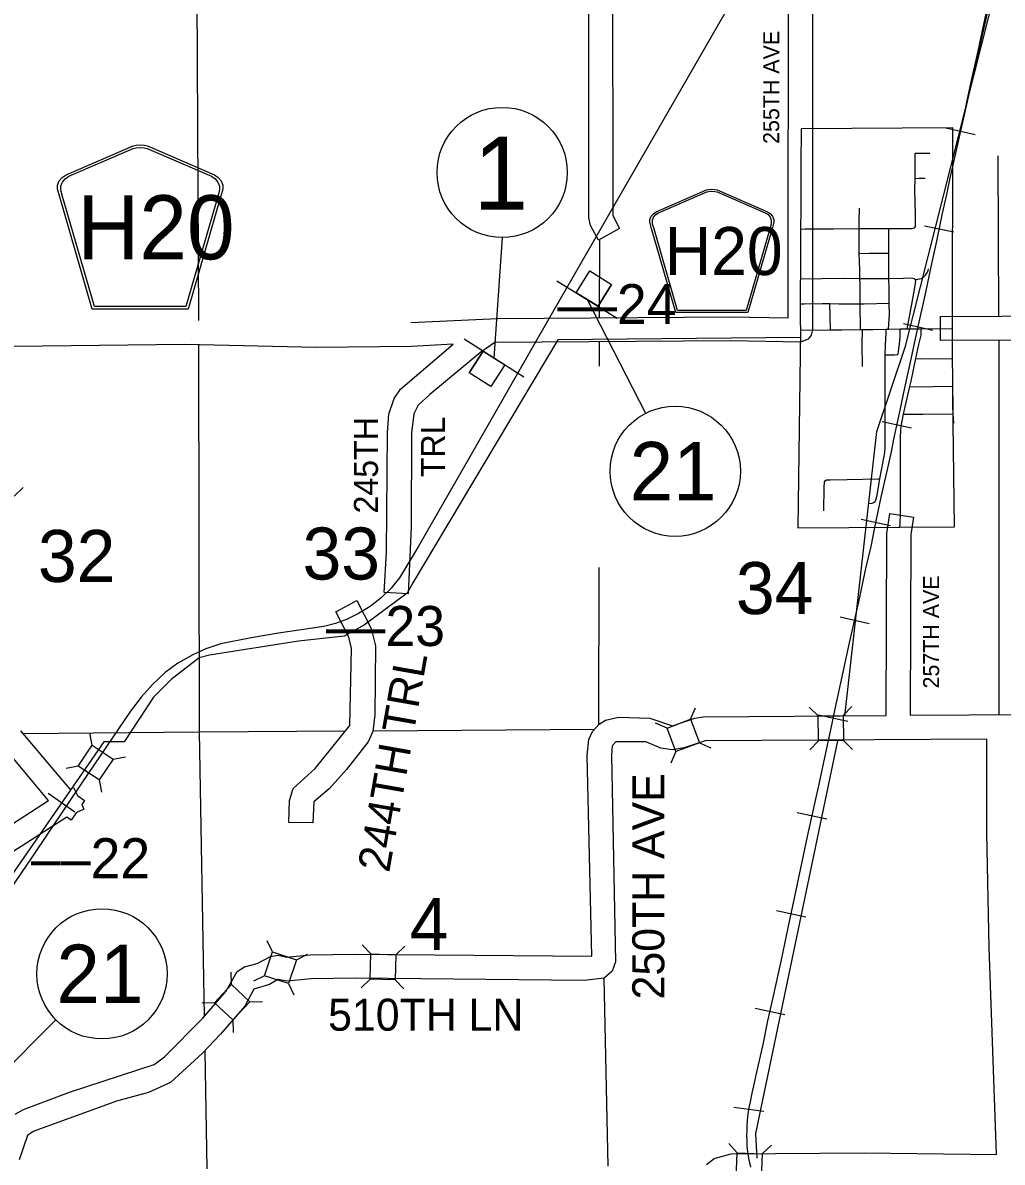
# Model space of a CAD drawing. Extents: x 10133 to 81668, y 5524 to 11018.
# Drawn here: x 18585.8 to 18891.5, y 8825.6 to 9181.4 of the extents above; entities that cross this region are included whole.
import ezdxf

# ---------------------------------------------------------------- set-up
doc = ezdxf.new("R2010")
doc.units = 0
for name, color, linetype in [('Default', 7, 'Continuous'), ('DisBoundDim', 7, 'Continuous'), ('DisCLMLOR', 7, 'Continuous'), ('DisCLMLSUR', 7, 'Continuous'), ('trf_SignNumber_Text', 7, 'Continuous')]:
    doc.layers.add(name, color=color, linetype=linetype)

msp = doc.modelspace()

# ---------------------------------------------------------------- linework, layer by layer
at = {"layer": 'Default'}
for p, q in [((18883.08, 9146.4), (18873.93, 9148.47)), ((18876.38, 9115.97), (18867.2, 9117.87)), ((18869.8, 9085.35), (18860.65, 9087.38)), ((18863.22, 9054.81), (18854.06, 9056.83)), ((18842.35, 8964.85), (18852.34, 9053.78)), ((18842.35, 8964.85), (18852.34, 9053.78)), ((18583.05, 9033.52), (18585.84, 9036.26)), ((18856.6, 9024.29), (18847.43, 9026.27)), ((18850, 8993.68), (18840.87, 8995.79)), ((18794.18, 8963.89), (18795.79, 8967.45)), ((18833.99, 8964.94), (18831.18, 8967.66)), ((18841.81, 8965.06), (18844.54, 8967.87)), ((18843.3, 8963.22), (18834.13, 8965.21)), ((18607.43, 8955.79), (18606.67, 8959.63)), ((18786.86, 8961.12), (18783.3, 8962.73)), ((18796.95, 8956.57), (18800.52, 8954.96)), ((18834.11, 8957.12), (18831.39, 8954.31)), ((18841.93, 8957.24), (18844.74, 8954.51)), ((18789.63, 8953.8), (18788.02, 8950.24)), ((18603.08, 8949.29), (18599.24, 8948.53)), ((18613.94, 8951.44), (18617.78, 8952.2)), ((18609.59, 8944.94), (18610.35, 8941.1)), ((18601.99, 8934.94), (18593.7, 8940.68)), ((18836.69, 8932.69), (18827.52, 8934.65)), ((18830.17, 8902.15), (18820.99, 8904.07)), ((18663.74, 8891.25), (18661.99, 8894.76)), ((18694.39, 8890.6), (18691.7, 8893.44)), ((18702.22, 8890.39), (18705.05, 8893.09)), ((18671.16, 8888.77), (18674.66, 8890.51)), ((18650.93, 8881.05), (18650.81, 8884.96)), ((18661.25, 8883.83), (18657.75, 8882.09)), ((18668.67, 8881.35), (18670.41, 8877.85)), ((18694.19, 8882.78), (18691.35, 8880.08)), ((18702.01, 8882.57), (18704.7, 8879.73)), ((18645.57, 8875.35), (18641.66, 8875.23)), ((18656.63, 8875.69), (18660.54, 8875.81)), ((18823.58, 8871.56), (18814.42, 8873.57)), ((18651.27, 8869.99), (18651.39, 8866.07)), ((18817.04, 8841.37), (18807.76, 8842.66)), ((18808.75, 8828.55), (18806.11, 8831.43)), ((18816.57, 8828.22), (18819.45, 8830.87))]:
    msp.add_line(p, q, dxfattribs=at)
for points in [[(18706.9, 9087.83), (18733.89, 9089.06), (18806.81, 9089.56), (18824.72, 9089.23), (18824.75, 9207.22), (18823.61, 9212.38), (18819.98, 9218.12), (18824.95, 9221.42), (18824.62, 9268.34), (18801, 9268.34), (18801.02, 9275.84), (18886.94, 9275.81), (18886.45, 9366.81)], [(18639.97, 9210.03), (18640.62, 9088.43)], [(18852.34, 9053.78), (18861.28, 9080.37), (18894.42, 9211.45)], [(18852.34, 9053.78), (18861.28, 9080.37), (18894.42, 9211.45)], [(18832.25, 9207.36), (18832.24, 9085.5), (18831.9, 9083.89), (18830.91, 9082.59), (18828.47, 9081.71), (18806.79, 9082.06), (18733.07, 9081.53), (18728.74, 9078.49), (18712.78, 9065.27), (18709.19, 9061.95), (18707.8, 9059.33), (18707.06, 9053.36), (18706.94, 9023.98), (18706.04, 9003.03), (18698.55, 9003.47), (18699.26, 9015.94), (18699.56, 9053.49), (18700.03, 9059.2), (18701.65, 9064.03), (18703.61, 9066.96), (18720.06, 9081.03), (18707.1, 9080.33), (18677.41, 9080.02), (18636.35, 9080.95), (18583.04, 9080.34)], [(18769.85, 9201.5), (18769.95, 9121.24), (18772.07, 9117.14), (18765.51, 9113.5), (18762.98, 9118.08), (18762.49, 9120.46), (18762.43, 9187.34)], [(18814.36, 9200.97), (18770.52, 9124.8), (18746.78, 9083.34), (18723.6, 9042.93), (18709.21, 9017.78), (18703.32, 9008.07), (18700.69, 9004.81), (18697.6, 9001.78), (18694.19, 8999.12), (18690.5, 8996.88), (18686.8, 8995.09), (18683.32, 8993.77), (18679.7, 8992.88), (18665.53, 8990.74), (18657.05, 8989.32), (18647.52, 8987.43), (18642.87, 8985.87), (18638.82, 8984.05), (18634.18, 8981.37), (18630.23, 8978.47), (18626.27, 8974.8), (18622.65, 8970.78), (18619.41, 8966.45), (18604.18, 8944.04), (18588.65, 8920.98), (18568.86, 8892.04)], [(18813.03, 8823.99), (18812.44, 8826.8), (18812.12, 8828.87), (18811.92, 8830.64), (18811.82, 8832.57), (18811.75, 8833.92), (18811.85, 8835.55), (18811.89, 8837), (18811.98, 8838.4), (18812.12, 8839.81), (18812.31, 8841.39), (18812.48, 8842.57), (18812.87, 8844.43), (18813.43, 8847.09), (18814.15, 8850.33), (18814.9, 8853.71), (18816.87, 8862.29), (18818.37, 8869.7), (18819.98, 8877), (18822.57, 8888.77), (18824.67, 8898.73), (18825.69, 8903.62), (18827.02, 8910.03), (18829.45, 8921.34), (18830.73, 8927.24), (18832.96, 8937.63), (18834.3, 8943.62), (18836.13, 8951.98), (18837.94, 8960.63), (18839.35, 8967.12), (18841.84, 8978.62), (18843.83, 8987.79), (18846.78, 9000.57), (18848.95, 9010.93), (18850.58, 9017.87), (18851.7, 9023.82), (18853.73, 9033.21), (18855.47, 9040.94), (18856.88, 9047.46), (18857.66, 9051.4), (18859.66, 9060.44), (18861.07, 9067.39), (18863.17, 9076.82), (18864.94, 9085.08), (18867.75, 9097.73), (18869.59, 9106.65), (18871.03, 9113.23), (18872.71, 9121.37), (18874.15, 9127.78), (18875.22, 9133.01), (18876.02, 9136.54), (18877.91, 9144.82), (18889.83, 9197.39)], [(18813.03, 8823.99), (18812.44, 8826.8), (18812.12, 8828.87), (18811.92, 8830.64), (18811.82, 8832.57), (18811.75, 8833.92), (18811.85, 8835.55), (18811.89, 8837), (18811.98, 8838.4), (18812.12, 8839.81), (18812.31, 8841.39), (18812.48, 8842.57), (18812.87, 8844.43), (18813.43, 8847.09), (18814.15, 8850.33), (18814.9, 8853.71), (18816.87, 8862.29), (18818.37, 8869.7), (18819.98, 8877), (18822.57, 8888.77), (18824.67, 8898.73), (18825.69, 8903.62), (18827.02, 8910.03), (18829.45, 8921.34), (18830.73, 8927.24), (18832.96, 8937.63), (18834.3, 8943.62), (18836.13, 8951.98), (18837.94, 8960.63), (18839.35, 8967.12), (18841.84, 8978.62), (18843.83, 8987.79), (18846.78, 9000.57), (18848.95, 9010.93), (18850.58, 9017.87), (18851.7, 9023.82), (18853.73, 9033.21), (18855.47, 9040.94), (18856.88, 9047.46), (18857.66, 9051.4), (18859.66, 9060.44), (18861.07, 9067.39), (18863.17, 9076.82), (18864.94, 9085.08), (18867.75, 9097.73), (18869.59, 9106.65), (18871.03, 9113.23), (18872.71, 9121.37), (18874.15, 9127.78), (18875.22, 9133.01), (18876.02, 9136.54), (18877.91, 9144.82), (18879.42, 9151.47), (18880.44, 9156.58), (18881.81, 9162.94), (18883.97, 9172.54), (18884.89, 9177.03), (18887.09, 9187.22)], [(18813.03, 8823.99), (18812.44, 8826.8), (18812.12, 8828.87), (18811.92, 8830.64), (18811.82, 8832.57), (18811.75, 8833.92), (18811.85, 8835.55), (18811.89, 8837), (18811.98, 8838.4), (18812.12, 8839.81), (18812.31, 8841.39), (18812.48, 8842.57), (18812.87, 8844.43), (18813.43, 8847.09), (18814.15, 8850.33), (18814.9, 8853.71), (18816.87, 8862.29), (18818.37, 8869.7), (18819.98, 8877), (18822.57, 8888.77), (18824.67, 8898.73), (18825.69, 8903.62), (18827.02, 8910.03), (18829.45, 8921.34), (18830.73, 8927.24), (18832.96, 8937.63), (18834.3, 8943.62), (18836.13, 8951.98), (18837.94, 8960.63), (18839.35, 8967.12), (18841.84, 8978.62), (18843.83, 8987.79), (18846.78, 9000.57), (18848.95, 9010.93), (18850.58, 9017.87), (18851.7, 9023.82), (18853.73, 9033.21), (18855.47, 9040.94), (18856.88, 9047.46), (18857.66, 9051.4), (18859.66, 9060.44), (18861.07, 9067.39), (18863.17, 9076.82), (18864.94, 9085.08), (18867.75, 9097.73), (18869.59, 9106.65), (18871.03, 9113.23), (18872.71, 9121.37), (18874.15, 9127.78), (18875.22, 9133.01), (18876.02, 9136.54), (18877.91, 9144.82), (18879.42, 9151.47), (18880.44, 9156.58), (18881.81, 9162.94), (18883.97, 9172.54), (18884.89, 9177.03), (18887.09, 9187.22)], [(18864.28, 9132.8), (18864.3, 9134.84), (18864.27, 9140.29), (18864.36, 9140.63), (18868.89, 9140.66)], [(18890.1, 9139.8), (18890.36, 9089.74)], [(18856.1, 9117.16), (18863.16, 9117.11), (18864.02, 9117.36), (18864.05, 9117.38), (18864.18, 9117.48), (18864.39, 9117.82), (18864.45, 9118.56), (18864.39, 9121.55), (18864.24, 9129.1), (18864.28, 9132.8)], [(18864.28, 9132.8), (18865.59, 9132.86), (18867.41, 9132.92)], [(18846.83, 9117.17), (18846.85, 9119.21), (18846.94, 9123.46)], [(18828.53, 9116.98), (18829.84, 9117.02), (18838.87, 9117.08), (18846.83, 9117.17)], [(18846.88, 9109.38), (18846.79, 9112.86), (18846.83, 9117.17)], [(18846.83, 9117.17), (18850.03, 9117.2), (18856.1, 9117.16)], [(18856.08, 9109.5), (18856.1, 9117.16)], [(18765.76, 9113.64), (18765.67, 9089.28)], [(18846.88, 9109.38), (18850.06, 9109.5), (18856.08, 9109.5)], [(18847.09, 9101.56), (18847.01, 9104.32), (18846.88, 9109.38)], [(18856.12, 9101.58), (18856.07, 9105.33), (18856.08, 9109.5)], [(18864.36, 9101.19), (18865.16, 9101.3), (18866.15, 9101.57), (18866.89, 9101.97), (18867.57, 9102.53), (18868, 9103.18), (18868.4, 9103.92), (18868.52, 9104.53)], [(18828.47, 9101.47), (18841.83, 9101.64), (18847.09, 9101.56)], [(18847.09, 9101.56), (18850.52, 9101.51), (18856.12, 9101.58)], [(18847.18, 9093.65), (18847.18, 9094.99), (18847.13, 9100), (18847.09, 9101.56)], [(18856.12, 9101.58), (18860.63, 9101.64), (18863.16, 9101.7), (18863.95, 9101.54), (18863.96, 9101.54), (18864.36, 9101.19)], [(18856.22, 9093.82), (18856.16, 9098.43), (18856.12, 9101.58)], [(18861.82, 9085.82), (18862.59, 9089.54), (18863.88, 9096.97), (18864.39, 9099.94), (18864.52, 9100.87), (18864.36, 9101.19)], [(18828.46, 9093.62), (18829.74, 9093.62), (18835.39, 9093.74), (18837.72, 9093.69)], [(18837.9, 9085.48), (18837.72, 9093.69)], [(18837.72, 9093.69), (18840.44, 9093.62), (18847.18, 9093.65)], [(18847.18, 9093.65), (18848.39, 9093.65), (18856.22, 9093.82)], [(18847.21, 9085.6), (18847.18, 9093.65)], [(18856.02, 9085.74), (18856.27, 9090.43), (18856.22, 9093.82)], [(18917.78, 9082.38), (18872.17, 9082.13), (18872.21, 9089.63), (18948.64, 9090.08)], [(18828.49, 9085.46), (18831.42, 9085.44), (18837.9, 9085.48), (18841.38, 9085.5), (18847.21, 9085.6), (18847.85, 9085.61), (18848.47, 9085.62), (18851.18, 9085.66), (18855.12, 9085.72), (18855.28, 9085.73), (18856.02, 9085.74), (18859.62, 9085.79), (18859.72, 9085.79), (18860.65, 9085.81), (18861.82, 9085.82), (18863.53, 9085.84)], [(18847.85, 9074.09), (18847.79, 9080.94), (18847.85, 9085.61)], [(18855, 9077.73), (18855.58, 9077.75), (18857.83, 9077.71), (18858.69, 9077.84), (18859.03, 9078.05), (18859.15, 9078.61), (18859.24, 9079.63), (18859.46, 9081.04), (18859.65, 9083.29), (18859.62, 9085.79)], [(18855, 9077.73), (18855.04, 9080.78), (18855.25, 9084.51), (18855.28, 9085.73)], [(18859.5, 9023.87), (18859.65, 9024.82), (18859.71, 9028.12), (18859.77, 9037.24), (18859.74, 9041.65), (18859.74, 9052.04), (18859.8, 9054.19), (18859.95, 9055.46), (18860.32, 9057.46), (18860.7, 9059.19), (18861.19, 9061.44), (18862.67, 9067.79), (18863.08, 9069.53), (18864.54, 9076.51), (18865.45, 9080.91), (18866.19, 9083.83), (18866.19, 9085.87)], [(18863.53, 9085.84), (18866.19, 9085.87)], [(18866.19, 9085.87), (18868.6, 9085.9), (18875.94, 9085.86)], [(18876, 9076.59), (18875.97, 9079.58), (18875.94, 9085.86)], [(18828.53, 9083.11), (18752.79, 9082.4), (18707.54, 9006.53), (18705.75, 9003.26), (18692.45, 8993.43), (18686.1, 8989.85), (18671.81, 8988.26), (18644.01, 8983.89), (18640.84, 8983.09), (18632.1, 8976.34), (18626.55, 8970.78), (18617.42, 8956.87), (18611.06, 8956.87), (18570.57, 8898.48), (18553.9, 8871.87), (18506.65, 8873.05)], [(18640.64, 9080.93), (18640.77, 8959.94)], [(18765.65, 9081.77), (18765.63, 9074.19)], [(18890.38, 9082.23), (18890.45, 8965.2)], [(18853.33, 9038.95), (18853.94, 9042.2), (18854.81, 9047.17), (18854.93, 9048.74), (18854.99, 9050.22), (18854.96, 9053.45), (18854.96, 9059.1), (18854.9, 9064.58), (18854.97, 9075.57), (18855, 9077.73)], [(18864.54, 9076.51), (18866.18, 9076.45), (18876, 9076.59)], [(18876.08, 9067.96), (18876.08, 9068.16), (18876.06, 9070.36), (18876, 9076.59)], [(18862.67, 9067.79), (18863.9, 9067.76), (18876.08, 9067.96)], [(18876.2, 9059.24), (18876.08, 9061.69), (18876.08, 9067.96)], [(18860.7, 9059.19), (18861.68, 9059.13), (18866.7, 9059.16), (18876.2, 9059.24)], [(18876.35, 9056.41), (18876.2, 9059.24)], [(18835.79, 9029.04), (18835.88, 9036.28), (18836, 9038.01), (18836.19, 9038.35), (18836.26, 9038.4), (18836.65, 9038.63), (18837.76, 9038.66), (18843.06, 9038.81), (18852.77, 9038.94), (18853.33, 9038.95)], [(18849.66, 9031.38), (18850.24, 9031.23), (18850.92, 9031.35), (18851.35, 9031.57), (18851.78, 9031.91), (18852.06, 9032.37), (18852.49, 9033.85), (18853.11, 9037.76), (18853.33, 9038.95)], [(18583.42, 8840.59), (18585.94, 8842.05), (18600.28, 8847.44), (18626.73, 8856.06), (18629.96, 8858.51), (18641.9, 8870.6), (18649.1, 8878.87), (18652.67, 8885.1), (18655.01, 8886.56), (18658.95, 8887.65), (18663.05, 8889.81), (18665.48, 8890.19), (18668.02, 8889.64), (18675.45, 8890.31), (18689.62, 8890.56), (18763.34, 8889.94), (18761.97, 8952.58), (18762.45, 8957.55), (18763.55, 8960.04), (18765.63, 8962.38), (18767.66, 8963.65), (18771.71, 8964.52), (18781.48, 8964.23), (18788.52, 8961.84), (18795.56, 8964.25), (18798.11, 8964.68), (18855.3, 8965.05), (18855.43, 9021.86), (18856.36, 9028.14), (18863.77, 9027.01), (18862.93, 9021.56), (18862.8, 8965.18), (18918.02, 8965.49)], [(18765.52, 9011.33), (18765.44, 8962.16)], [(18668.83, 8931.7), (18669.02, 8938.49), (18670.15, 8942.27), (18677.03, 8948.53), (18687.79, 8961.96), (18688.39, 8985.98), (18687.51, 8989.56), (18683.47, 8997.42), (18690.04, 9001.03), (18694.51, 8992.28), (18695.84, 8986.84), (18695.65, 8965.25), (18695.04, 8960.04), (18693.57, 8956.83), (18686.75, 8948.25), (18681.39, 8942.17), (18676.55, 8938.15), (18676.33, 8931.52), (18668.83, 8931.7)], [(18585.01, 8960.33), (18600.48, 8942.06), (18601.62, 8942.6), (18602.8, 8940.13), (18605.06, 8938.58), (18604.15, 8937.26), (18604.84, 8935.83), (18602.36, 8934.65), (18600.81, 8932.4), (18599.51, 8933.29), (18579.72, 8920.68)], [(18585.78, 8959.44), (18640.77, 8959.94), (18686.63, 8960.25)], [(18585.78, 8959.44), (18640.77, 8959.94)], [(18640.77, 8959.94), (18686.63, 8960.25)], [(18640.77, 8959.94), (18642.34, 8871.11)], [(18695.1, 8960.3), (18764.2, 8960.76)], [(18695.2, 8960.3), (18764.13, 8960.76)], [(18573.56, 8925.53), (18593.82, 8938.5), (18577.42, 8957.98)], [(18799.16, 8824.91), (18801.6, 8826.71), (18806.92, 8828.21), (18848.41, 8828.52), (18889.68, 8828), (18887.41, 8892.59), (18886.67, 8928.39), (18886.71, 8957.71), (18798.74, 8957.2), (18792.18, 8954.96), (18788.48, 8954.33), (18784.93, 8954.89), (18780.26, 8956.83), (18770.86, 8956.84), (18769.7, 8955.6), (18769.47, 8952.67), (18770.82, 8888.19), (18769.72, 8885.24), (18767.2, 8883.07), (18760.97, 8882.35), (18689.6, 8883.06), (18675.76, 8882.82), (18668.29, 8882.14), (18665.35, 8882.63), (18662.78, 8881.11), (18657.9, 8879.62), (18655.05, 8874.29), (18647.48, 8865.59), (18641.88, 8859.58), (18631.85, 8850.44), (18625.01, 8847.34), (18615.01, 8844.62), (18588.97, 8835.18), (18587.26, 8833.87), (18584.66, 8826.27)], [(18814.98, 8826.84), (18814.56, 8834.53), (18840.2, 8957.15)], [(18814.98, 8826.84), (18814.56, 8834.53), (18840.2, 8957.15)], [(18767.09, 8883.04), (18768.33, 8824.32)], [(18642.53, 8860.27), (18643.17, 8823.5)]]:
    msp.add_lwpolyline(points, dxfattribs=at)
for points in [[(18876.04, 9148.59), (18828.7, 9148.28), (18828.63, 9136.81), (18828.6, 9123.18), (18828.53, 9116.98), (18828.51, 9115.32), (18828.47, 9101.47), (18828.46, 9100.67), (18828.46, 9093.62), (18828.46, 9088.15), (18828.49, 9085.46), (18827.72, 9023.66), (18859.5, 9023.87), (18876.6, 9023.98), (18876.22, 9056.4), (18876.2, 9059.24), (18876.19, 9061.7), (18876.08, 9067.96), (18876.06, 9070.36), (18876, 9076.59), (18875.97, 9079.58), (18875.94, 9085.67)], [(18607.43, 9091.98), (18597.19, 9127.34), (18596.7, 9128.99), (18596.61, 9129.72), (18596.61, 9130.7), (18597.14, 9131.99), (18598.05, 9133.05), (18599.25, 9133.89), (18620.16, 9142.93), (18621.1, 9143.13), (18622.4, 9143.25), (18623.7, 9143.13), (18624.64, 9142.93), (18645.55, 9133.89), (18646.75, 9133.05), (18647.66, 9131.99), (18648.19, 9130.7), (18648.19, 9129.72), (18648.1, 9128.99), (18647.61, 9127.34), (18637.37, 9091.98)], [(18608.16, 9092.77), (18598.19, 9127.18), (18597.73, 9128.76), (18597.64, 9129.47), (18597.64, 9130.41), (18598.15, 9131.64), (18599.02, 9132.66), (18600.17, 9133.46), (18620.25, 9142.14), (18621.15, 9142.34), (18622.4, 9142.45), (18623.65, 9142.34), (18624.55, 9142.14), (18644.62, 9133.46), (18645.77, 9132.66), (18646.65, 9131.64), (18647.16, 9130.41), (18647.16, 9129.47), (18647.07, 9128.76), (18646.6, 9127.18), (18636.64, 9092.77)], [(18789.62, 9090.97), (18781.94, 9117.49), (18781.57, 9118.72), (18781.5, 9119.27), (18781.5, 9120.01), (18781.9, 9120.97), (18782.58, 9121.77), (18783.48, 9122.4), (18799.16, 9129.18), (18799.87, 9129.33), (18800.85, 9129.42), (18801.82, 9129.33), (18802.53, 9129.18), (18818.21, 9122.4), (18819.11, 9121.77), (18819.79, 9120.97), (18820.19, 9120.01), (18820.19, 9119.27), (18820.12, 9118.72), (18819.76, 9117.49), (18812.07, 9090.97)], [(18790.17, 9091.56), (18782.69, 9117.37), (18782.34, 9118.55), (18782.28, 9119.08), (18782.28, 9119.79), (18782.66, 9120.71), (18783.31, 9121.48), (18784.18, 9122.08), (18799.23, 9128.59), (18799.91, 9128.74), (18800.85, 9128.82), (18801.78, 9128.74), (18802.46, 9128.59), (18817.52, 9122.08), (18818.38, 9121.48), (18819.03, 9120.71), (18819.41, 9119.79), (18819.41, 9119.08), (18819.35, 9118.55), (18819, 9117.37), (18811.52, 9091.56)], [(18786.86, 8961.12), (18794.18, 8963.89), (18796.95, 8956.57), (18789.63, 8953.8)], [(18833.99, 8964.94), (18841.81, 8965.06), (18841.93, 8957.24), (18834.11, 8957.12)], [(18603.08, 8949.29), (18607.43, 8955.79), (18613.94, 8951.44), (18609.59, 8944.94)], [(18663.74, 8891.25), (18671.16, 8888.77), (18668.67, 8881.35), (18661.25, 8883.83)], [(18694.39, 8890.6), (18702.22, 8890.39), (18702.01, 8882.57), (18694.19, 8882.78)], [(18645.57, 8875.35), (18650.93, 8881.05), (18656.63, 8875.69), (18651.27, 8869.99)], [(18808.75, 8828.55), (18816.57, 8828.22), (18816.24, 8820.4), (18808.42, 8820.73)]]:
    msp.add_lwpolyline(points, close=True, dxfattribs=at)
at = {"layer": 'DisBoundDim'}
for p, q in [((18758.52, 9097.08), (18762.72, 9103.89)), ((18762.72, 9103.89), (18769.53, 9099.68)), ((18752.5, 9100.8), (18771.33, 9089.16)), ((18765.32, 9092.88), (18769.53, 9099.68)), ((18742.15, 9070.75), (18723.48, 9082.64)), ((18729.44, 9078.84), (18725.14, 9072.09)), ((18736.19, 9074.54), (18731.89, 9067.8)), ((18731.89, 9067.8), (18725.14, 9072.09))]:
    msp.add_line(p, q, dxfattribs=at)
at = {"layer": 'DisCLMLOR'}
for p, q in [((18758.52, 9097.08), (18762.72, 9103.89)), ((18758.52, 9097.08), (18762.72, 9103.89)), ((18758.52, 9097.08), (18762.72, 9103.89)), ((18758.52, 9097.08), (18762.72, 9103.89)), ((18762.72, 9103.89), (18769.53, 9099.68)), ((18762.72, 9103.89), (18769.53, 9099.68)), ((18762.72, 9103.89), (18769.53, 9099.68)), ((18762.72, 9103.89), (18769.53, 9099.68)), ((18769.53, 9099.68), (18765.32, 9092.88)), ((18769.53, 9099.68), (18765.32, 9092.88)), ((18769.53, 9099.68), (18765.32, 9092.88)), ((18769.53, 9099.68), (18765.32, 9092.88)), ((18765.32, 9092.88), (18758.52, 9097.08)), ((18765.32, 9092.88), (18758.52, 9097.08)), ((18765.32, 9092.88), (18758.52, 9097.08)), ((18765.32, 9092.88), (18758.52, 9097.08)), ((18725.14, 9072.09), (18729.44, 9078.84)), ((18725.14, 9072.09), (18729.44, 9078.84)), ((18725.14, 9072.09), (18729.44, 9078.84)), ((18725.14, 9072.09), (18729.44, 9078.84)), ((18729.44, 9078.84), (18736.19, 9074.54)), ((18729.44, 9078.84), (18736.19, 9074.54)), ((18729.44, 9078.84), (18736.19, 9074.54)), ((18729.44, 9078.84), (18736.19, 9074.54)), ((18736.19, 9074.54), (18731.89, 9067.8)), ((18736.19, 9074.54), (18731.89, 9067.8)), ((18736.19, 9074.54), (18731.89, 9067.8)), ((18736.19, 9074.54), (18731.89, 9067.8)), ((18731.89, 9067.8), (18725.14, 9072.09)), ((18731.89, 9067.8), (18725.14, 9072.09)), ((18731.89, 9067.8), (18725.14, 9072.09)), ((18731.89, 9067.8), (18725.14, 9072.09))]:
    msp.add_line(p, q, dxfattribs=at)
at = {"layer": 'DisCLMLSUR'}
for p, q in [((18735.39, 9114.33), (18732.81, 9076.69)), ((18761.92, 9094.98), (18780.14, 9059.44)), ((18563.07, 8837.01), (18596.11, 8870.02))]:
    msp.add_line(p, q, dxfattribs=at)
at = {"layer": 'trf_SignNumber_Text'}
for centre in [(18735.39, 9134.66), (18789.41, 9041.35), (18610.48, 8884.39)]:
    msp.add_circle(centre, 20.33, dxfattribs=at)

# ---------------------------------------------------------------- texts
at = {"layer": 'Default'}
for s, height, rotation, p in [('255TH AVE', 5, 90, (18821.88, 9143.57)), ('245TH', 7.5, 90, (18696.61, 9028.16)), ('TRL', 7.5, 90, (18717.53, 9039.5)), ('33', 16.25, 0.0085, (18673.09, 9007.53)), ('32', 16.25, 0.008, (18590.48, 9006.77)), ('34', 16.25, 0.0093, (18808.36, 8996.74)), ('257TH AVE', 5, 90, (18871.8, 8973.52)), ('244TH TRL', 10, 80, (18700.1, 8915.76)), ('250TH AVE', 10, 90, (18786.01, 8876.42)), ('4', 16.25, 0.0086, (18706.56, 8891.84))]:
    msp.add_text(s, height=height, rotation=rotation, dxfattribs=at).set_placement(p)
for s, height, p in [('H20', 20, (18602.81, 9107.52)), ('H20', 15, (18786.15, 9102.62)), ('‒‒24', 12.5, (18752.61, 9087.29)), ('‒‒23', 12.5, (18680.37, 8986.77)), ('‒‒22', 12.5, (18588.33, 8914.27)), ('510TH LN', 10, (18681.06, 8866.64))]:
    msp.add_text(s, height=height, dxfattribs=at).set_placement(p)
at = {"layer": 'trf_SignNumber_Text'}
for s, height, p in [('1', 22.82, (18726.49, 9123.05)), ('21', 18.258, (18775.18, 9032.23)), ('21', 18.258, (18596.25, 8875.26))]:
    msp.add_text(s, height=height, dxfattribs=at).set_placement(p)

doc.saveas('drawing.dxf')
